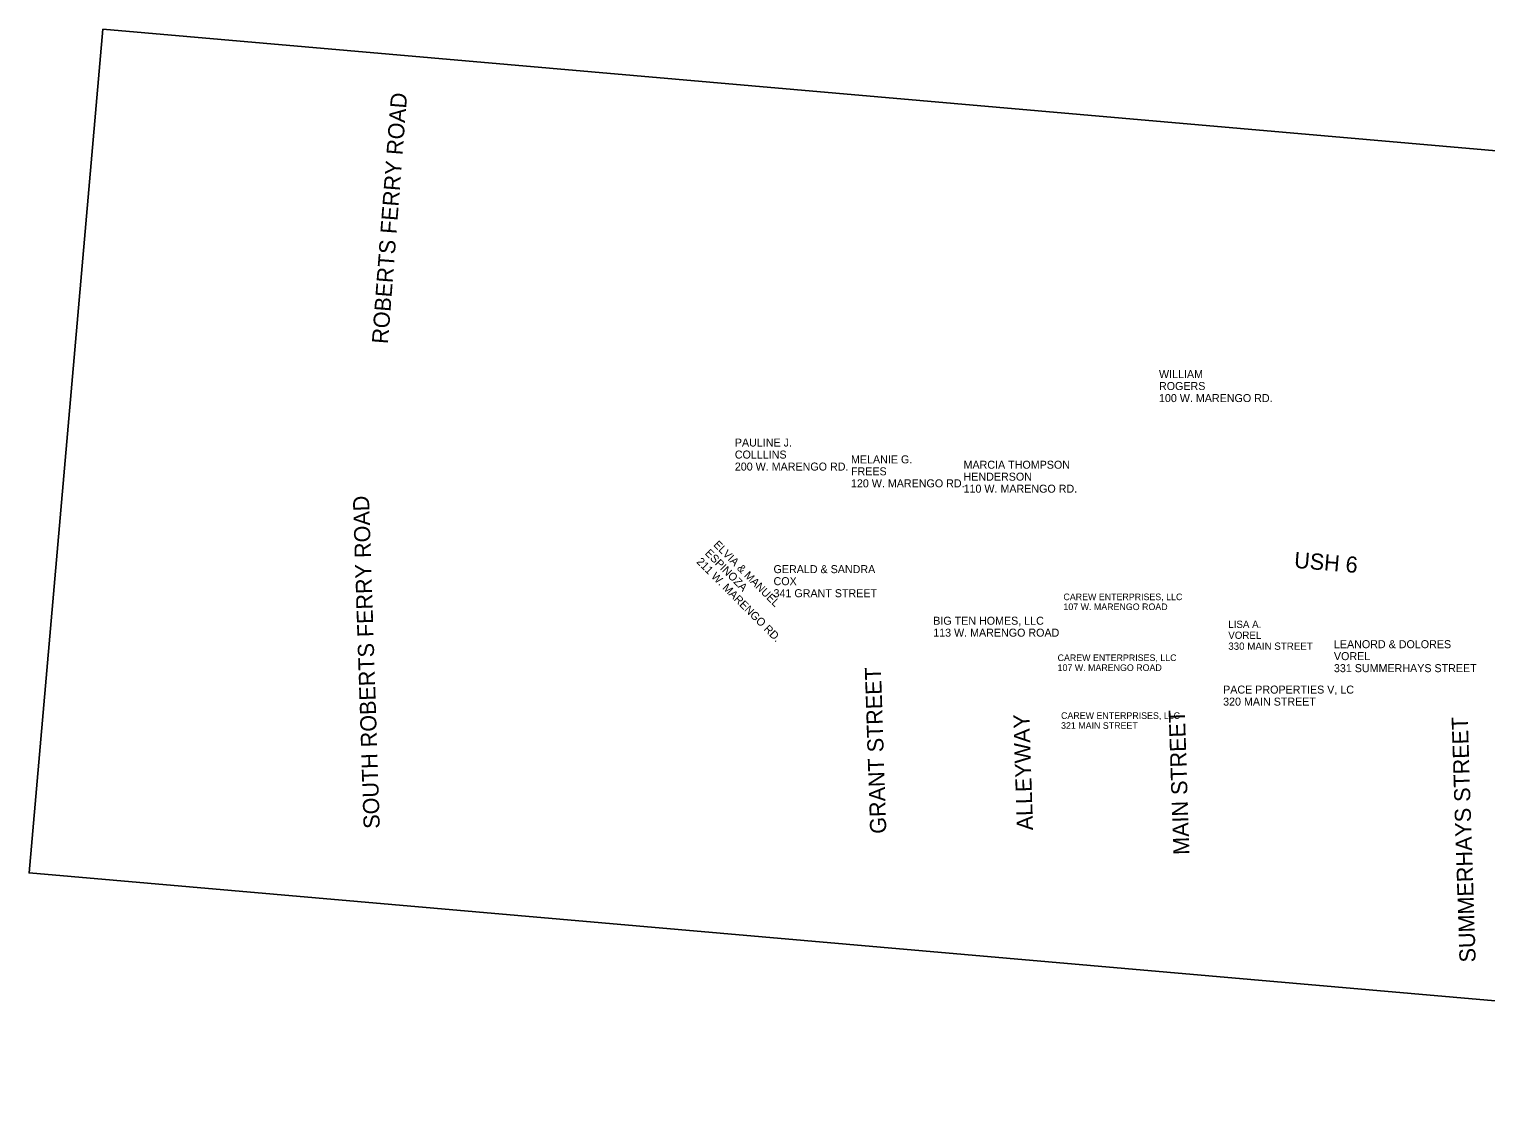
# Model space of a CAD drawing. Extents: x 20499598 to 20505777, y 7953097 to 7954577.
# Drawn here: x 20499598 to 20501318, y 7953308 to 7954577 of the extents above; entities that cross this region are included whole.
import ezdxf

# ---------------------------------------------------------------- set-up
doc = ezdxf.new("R2010")
doc.units = 0
for name, color, linetype in [('DisROW Property Lines', 7, 'Continuous'), ('NamedBoundary', 7, 'Continuous'), ('Text', 7, 'Continuous')]:
    doc.layers.add(name, color=color, linetype=linetype)

msp = doc.modelspace()

# ---------------------------------------------------------------- linework, layer by layer
at = {"layer": 'NamedBoundary'}
msp.add_lwpolyline([(20499685.1, 7954577.3), (20499598.1, 7953581.1), (20502721.2, 7953308.4), (20502808.2, 7954304.6)], close=True, dxfattribs=at)

# ---------------------------------------------------------------- texts
at = {"layer": 'DisROW Property Lines'}
for s, height, p in [('WILLIAM', 9.45, (20500931.8, 7954165.3)), ('ROGERS', 9.45, (20500931.8, 7954151.2)), ('100 W. MARENGO RD.', 9.449, (20500931.8, 7954137)), ('COLLLINS', 9.45, (20500431.1, 7954070.3)), ('PAULINE J.', 9.45, (20500431.1, 7954084.5)), ('200 W. MARENGO RD.', 9.449, (20500431.1, 7954056.1)), ('MELANIE G.', 9.45, (20500568.2, 7954064.6)), ('MARCIA THOMPSON', 9.449, (20500701.1, 7954058.3)), ('120 W. MARENGO RD.', 9.449, (20500568.2, 7954036.3)), ('FREES', 9.45, (20500568.2, 7954050.5)), ('HENDERSON', 9.45, (20500701.1, 7954044.2)), ('110 W. MARENGO RD.', 9.449, (20500701.1, 7954030)), ('GERALD & SANDRA', 9.449, (20500476.8, 7953935)), ('COX', 9.45, (20500476.8, 7953920.8)), ('341 GRANT STREET', 9.449, (20500476.8, 7953906.6)), ('CAREW ENTERPRISES, LLC', 7.808, (20500819, 7953903.1)), ('107 W. MARENGO ROAD', 7.808, (20500819, 7953891.4)), ('BIG TEN HOMES, LLC', 9.449, (20500665.3, 7953874.1)), ('LISA A. ', 8.6, (20501013.6, 7953870.3)), ('113 W. MARENGO ROAD', 9.449, (20500665.3, 7953860)), ('VOREL', 8.6, (20501013.6, 7953857.4)), ('LEANORD & DOLORES', 9.449, (20501138.3, 7953846.4)), ('CAREW ENTERPRISES, LLC', 7.808, (20500812.1, 7953831.2)), ('330 MAIN STREET', 8.601, (20501013.6, 7953844.5)), ('VOREL', 9.45, (20501138.3, 7953832.3)), ('107 W. MARENGO ROAD', 7.808, (20500812.1, 7953819.5)), ('331 SUMMERHAYS STREET', 9.449, (20501138.3, 7953818.1)), ('320 MAIN STREET', 9.449, (20501007.5, 7953778.6)), ('PACE PROPERTIES V, LC', 9.449, (20501007.5, 7953792.8)), ('CAREW ENTERPRISES, LLC', 7.808, (20500816.2, 7953762.9)), ('321 MAIN STREET', 7.808, (20500816.2, 7953751.2))]:
    msp.add_text(s, height=height, dxfattribs=at).set_placement(p)
for s, height, p in [('ESPINOZA', 9.45, (20500395.2, 7953957.9)), ('ELVIA & MANUEL', 9.449, (20500405.2, 7953967.9)), ('211 W. MARENGO RD.', 9.449, (20500385.2, 7953947.8))]:
    msp.add_text(s, height=height, rotation=314.9836, dxfattribs=at).set_placement(p)
at = {"layer": 'Text'}
for s, height, rotation, p in [('ROBERTS FERRY ROAD', 19.051, 85.5837, (20500021.6, 7954205.2)), ('SOUTH ROBERTS FERRY ROAD', 19.051, 91.8771, (20500012.1, 7953633.5)), ('USH 6', 19.05, 355.2944, (20501090.8, 7953941.3)), ('GRANT STREET', 19.051, 91.8771, (20500610, 7953627.6)), ('MAIN STREET', 19.051, 91.8771, (20500967.8, 7953602.7)), ('ALLEYWAY', 19.05, 91.8771, (20500783.2, 7953631.6)), ('SUMMERHAYS STREET', 19.051, 91.8771, (20501305.7, 7953475.7))]:
    msp.add_text(s, height=height, rotation=rotation, dxfattribs=at).set_placement(p)

doc.saveas('drawing.dxf')
